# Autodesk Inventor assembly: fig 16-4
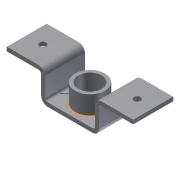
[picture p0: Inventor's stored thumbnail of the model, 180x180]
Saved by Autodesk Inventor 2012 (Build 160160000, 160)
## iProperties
Created: 2004-07
Part Number: fig 16-4
Document SubType Name: Weldment
Designer: CADCIM Technologies
Manufacturer: Standard
Standards Organization: Custom
Author: CADCIM Technologies
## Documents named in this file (3)
- C:\Users\CadCim\Documents\SAILESH\inventor-2011-fact-prt\c16-inv-2011-prt\c16_inv_2012_prt\fig 16-4.iam
- C:\Users\CadCim\Documents\SAILESH\inventor-2011-fact-prt\c16-inv-2011-prt\c16_inv_2012_prt\Bracket.ipt
- C:\Users\CadCim\Documents\SAILESH\inventor-2011-fact-prt\c16-inv-2011-prt\c16_inv_2012_prt\cylinder.ipt
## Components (2 placed, 2 different names)
1. Bracket:1 — Insert:1
2. cylinder:1 — Insert:1
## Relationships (1: Insert 1)
- Insert:1: Bracket:1 ↔ cylinder:1
